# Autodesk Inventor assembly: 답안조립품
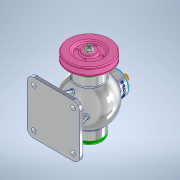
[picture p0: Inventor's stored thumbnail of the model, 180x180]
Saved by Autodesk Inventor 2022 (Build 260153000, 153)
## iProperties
Created: 2024-04
Part Number: 답안조립품
Document SubType Name: Assembly
Designer: user
Author: user
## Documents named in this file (16)
- C:\Users\user\Desktop\740406V1006\답안조립품.iam
- C:\Users\user\Desktop\740406V1006\본체.ipt
- C:\Users\user\Desktop\740406V1006\뒤커버.ipt
- C:\Users\user\Desktop\740406V1006\앞커버.ipt
- C:\Users\user\Desktop\740406V1006\상부커버.ipt
- C:\Users\user\Desktop\740406V1006\베어링- 6202.ipt
- KS B 2023 - 6202 - 15 x 35 x 11 - 7.8.ipt
- C:\Users\user\Desktop\740406V1006\편심축.ipt
- C:\Users\user\Desktop\740406V1006\칼라.ipt
- C:\Users\user\Desktop\740406V1006\키 4 x 4 x 12.ipt
- C:\Users\user\Desktop\740406V1006\오일실 15 30 7.ipt
- C:\Users\user\Desktop\740406V1006\V-벨트풀리.ipt
- C:\Users\user\Desktop\740406V1006\너트 M8.ipt
- C:\Users\user\Desktop\740406V1006\볼트 M4 x 16.ipt
- C:\Users\user\Desktop\740406V1006\볼트 M4 x 12.ipt
- C:\Users\user\Desktop\740406V1006\슬라이드.ipt
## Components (15 placed, 4 different names)
1. KS B 2023 - 6202 - 15 x 35 x 11 - 7.8:1
2. KS B 2023 - 6202 - 15 x 35 x 11 - 7.8:2
3. V-벨트풀리:1
4. ISO 4762 M4 x 16:1
5. ISO 4762 M4 x 16:2
6. ISO 4762 M4 x 16:3
7. ISO 4762 M4 x 16:4
8. ISO 4762 M4 x 16:5
9. ISO 4762 M4 x 16:6
10. ISO 4762 M4 x 16:7
11. ISO 4762 M4 x 16:8
12. KS B 1021 - 에 따름 ISO 1207 - 미터 A  M 4 x 12:1
13. KS B 1021 - 에 따름 ISO 1207 - 미터 A  M 4 x 12:2
14. KS B 1021 - 에 따름 ISO 1207 - 미터 A  M 4 x 12:3
15. KS B 1021 - 에 따름 ISO 1207 - 미터 A  M 4 x 12:4
